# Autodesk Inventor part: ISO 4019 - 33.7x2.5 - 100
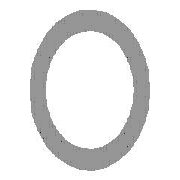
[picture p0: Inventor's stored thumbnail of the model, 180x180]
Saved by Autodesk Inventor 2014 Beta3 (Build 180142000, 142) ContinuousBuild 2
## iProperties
_CCFamilyMember: 8
_CCFamilyDisplayName: ISO 4019 (Circular Hollow Section - Cold Formed) - Sructural steels, Cold-formed, welded, structural hollow sections
_FrameMemberDoc: Frame Member File
_Version: 15.0.0
_GetPNFromCC: 1
Created: 2010-11
Part Number: ISO 4019 - 33.7x2.5 - 100
Material: Steel, Mild
Description: Sructural steels, Cold-formed, welded, structural hollow sections
Document SubType Name: Modeling
Standard: ISO
Designer: Beta-8540w
Standard Revision: Second edition 2001-09-01
Standards Organization: ISO
Language: en-US
Size Designation: 33.7x2.5
Categories: <MemberInstance><Categories><Category DisplayName="Structural Shapes" InternalName="089c4875-fa83-4c05-b084-43b9cc11f5ed" Mnemonic="GRDR"><CategoryParameter Dis
Stock Number: 33.7x2.5
Density: 7.86 g/cm^3
Appearance: Steel
IsCustomPart: 1
G_L: 100.000 mm
G_W: 33.700 mm
G_H: 33.700 mm
Author: Beta-8540w
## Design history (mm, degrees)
node "Start plane"
node "End plane"
sketch "Sketch"
  geometry: C1 r 14.35 at (0, 0); C2 r 16.85 at (0, 0); 2 further points
  constraints: 3 coincident, 2 centre point
  dimensions: "d0" = 33.7 diameter of C2 (= G_H); "d1" = 2.5 radial gap between concentric circles of C2 C1 (= G_T)
extrude "Body" new body sketch "Sketch" stored distance "d2" = 100 (= G_L); taper "d3" = 0 deg
node "Driven Length"
  sketch "Sketch3"
    geometry: L1 (0, 0)-(10, 0) reference
    constraints: 2 end point, 1 horizontal
  workplane "Work Plane3"
  sketch "Sketch4"
    geometry: L1 (-2, 0)-(12, 0) reference; L2 (-2, 100)-(12, 100) reference
    dimensions: "d7" = 100 distance between parallel lines of L1 L2 (derived)
body "Solid1"
other parameters: "G_H" = 33.7 [user parameter; used in 1 equation term], "G_T" = 2.5 [user parameter; used in 1 equation term], "G_L" = 100 (= d7) [user parameter; used in 1 equation term], "G_OFFSET_START" = 0 [user parameter; used in 1 equation term], "G_OFFSET_END" = 0 [user parameter; used in 1 equation term], "d4" = 0 (computed from G_OFFSET_START), "d6" = 90 deg, "MAS" = 0.192 [user parameter]
